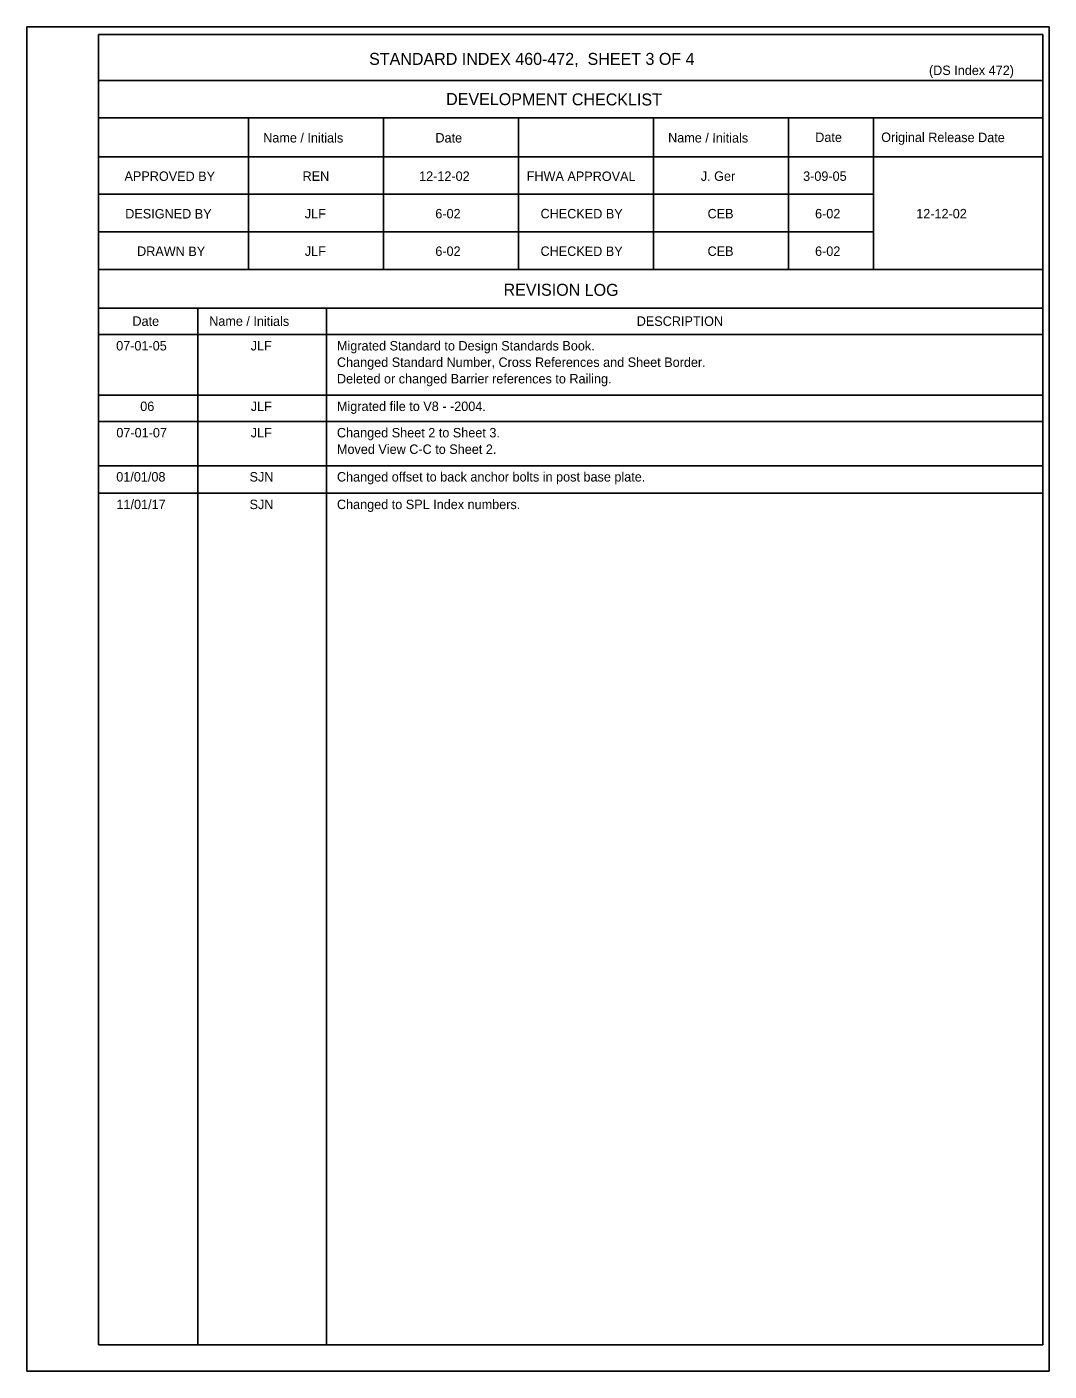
# Model space of a CAD drawing. Extents: x 21526.6 to 21595.9, y 56114.9 to 56157.2.
# Drawn here: x 21574.14 to 21595.95, y 56124.78 to 56153.45 of the extents above; entities that cross this region are included whole.
import ezdxf

# ---------------------------------------------------------------- set-up
doc = ezdxf.new("R2010")
doc.units = 0
doc.layers.add('Border', color=7, linetype='Continuous')
doc.layers.add('PlotBorder_dp', color=7, linetype='Continuous')

msp = doc.modelspace()

# ---------------------------------------------------------------- linework, layer by layer
at = {"layer": 'Border'}
for p, q in [((21595.814, 56152.307), (21575.667, 56152.307)), ((21595.814, 56151.507), (21575.667, 56151.507)), ((21578.867, 56151.507), (21578.867, 56148.279)), ((21581.747, 56151.507), (21581.747, 56148.279)), ((21584.627, 56151.507), (21584.627, 56148.279)), ((21587.507, 56151.507), (21587.507, 56148.279)), ((21590.387, 56151.507), (21590.387, 56148.279)), ((21592.202, 56151.507), (21592.202, 56148.279)), ((21595.814, 56150.679), (21575.667, 56150.679)), ((21592.202, 56149.879), (21575.667, 56149.879)), ((21592.202, 56149.079), (21575.667, 56149.079)), ((21595.814, 56148.279), (21575.667, 56148.279)), ((21595.814, 56147.451), (21575.667, 56147.451)), ((21577.787, 56147.451), (21577.787, 56125.345)), ((21580.529, 56147.451), (21580.529, 56125.345)), ((21595.814, 56146.887), (21575.667, 56146.887))]:
    msp.add_line(p, q, dxfattribs=at)
msp.add_lwpolyline([(21575.667, 56153.287), (21595.814, 56153.287), (21595.814, 56125.345), (21575.667, 56125.345)], close=True, dxfattribs=at)
at = {"layer": 'PlotBorder_dp'}
for p, q in [((21575.667, 56145.596), (21595.814, 56145.596)), ((21575.667, 56145.033), (21595.814, 56145.033)), ((21575.667, 56144.092), (21595.814, 56144.092)), ((21575.667, 56143.504), (21595.814, 56143.504)), ((21574.136, 56124.783), (21574.136, 56124.783))]:
    msp.add_line(p, q, dxfattribs=at)
msp.add_lwpolyline([(21574.136, 56153.45), (21595.95, 56153.45), (21595.95, 56124.783), (21574.136, 56124.783)], close=True, dxfattribs=at)

# ---------------------------------------------------------------- texts
at = {"layer": 'Border'}
for s, height, p in [('STANDARD INDEX 460-472,  SHEET 3 OF 4', 0.256, (21581.439, 56152.639)), ('(DS Index 472)', 0.2016, (21593.386, 56152.423)), ('REN', 0.2016, (21580.019, 56150.166)), ('12-12-02', 0.2016, (21582.506, 56150.166)), ('J. Ger', 0.2016, (21588.517, 56150.166)), ('3-09-05', 0.2016, (21590.7, 56150.166)), ('JLF', 0.2016, (21580.067, 56149.366)), ('6-02', 0.2016, (21582.852, 56149.366)), ('CEB', 0.2016, (21588.661, 56149.366)), ('6-02', 0.2016, (21590.955, 56149.366)), ('12-12-02', 0.2016, (21593.114, 56149.366)), ('JLF', 0.2016, (21580.067, 56148.566)), ('6-02', 0.2016, (21582.852, 56148.566)), ('CEB', 0.2016, (21588.661, 56148.566)), ('6-02', 0.2016, (21590.955, 56148.566)), ('DESCRIPTION', 0.2016, (21587.15, 56147.074)), ('07-01-05', 0.2016, (21576.042, 56146.549)), ('JLF', 0.2016, (21578.913, 56146.549)), ('Migrated Standard to Design Standards Book.', 0.2016, (21580.753, 56146.549)), ('Changed Standard Number, Cross References and Sheet Border.', 0.2016, (21580.753, 56146.198)), ('Deleted or changed Barrier references to Railing.', 0.2016, (21580.753, 56145.846)), ('06', 0.2016, (21576.555, 56145.258)), ('JLF', 0.2016, (21578.914, 56145.258)), ('Migrated file to V8 - -2004.', 0.2016, (21580.753, 56145.258)), ('07-01-07', 0.2016, (21576.046, 56144.695)), ('JLF', 0.2016, (21578.914, 56144.695)), ('Changed Sheet 2 to Sheet 3.', 0.2016, (21580.753, 56144.695)), ('Moved View C-C to Sheet 2.', 0.2016, (21580.753, 56144.343)), ('01/01/08', 0.2016, (21576.044, 56143.754)), ('SJN', 0.2016, (21578.888, 56143.754)), ('Changed offset to back anchor bolts in post base plate.', 0.2016, (21580.753, 56143.754)), ('11/01/17', 0.2016, (21576.048, 56143.166)), ('SJN', 0.2016, (21578.888, 56143.166)), ('Changed to SPL Index numbers.', 0.2016, (21580.753, 56143.166))]:
    msp.add_text(s, height=height, dxfattribs=at).set_placement(p)
for s, height, p in [('DEVELOPMENT CHECKLIST', 0.256, (21583.083, 56151.783)), ('Name / Initials', 0.2016, (21579.179, 56150.986)), ('Date', 0.2016, (21582.854, 56150.984)), ('Name / Initials', 0.2016, (21587.819, 56150.986)), ('Date', 0.2016, (21590.959, 56150.996)), ('Original Release Date', 0.2016, (21592.366, 56150.996)), ('APPROVED BY', 0.2016, (21576.219, 56150.167)), ('FHWA APPROVAL', 0.2016, (21584.802, 56150.167)), ('DESIGNED BY', 0.2016, (21576.236, 56149.366)), ('CHECKED BY', 0.2016, (21585.097, 56149.367)), ('DRAWN BY', 0.2016, (21576.488, 56148.566)), ('CHECKED BY', 0.2016, (21585.097, 56148.567)), ('REVISION LOG', 0.256, (21584.308, 56147.718)), ('Name / Initials', 0.2016, (21578.026, 56147.076)), ('Date', 0.2016, (21576.389, 56147.075))]:
    msp.add_text(s, height=height, rotation=359.8756, dxfattribs=at).set_placement(p)

doc.saveas('drawing.dxf')
